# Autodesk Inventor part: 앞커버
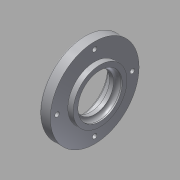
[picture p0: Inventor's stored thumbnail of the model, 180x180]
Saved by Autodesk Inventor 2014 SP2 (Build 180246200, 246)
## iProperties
Created: 2015-09
Part Number: 앞커버
Material: 알루미늄 6061
Document SubType Name: Modeling
Designer: mduedu
Density: 2.71 g/cm^3
Mass: 58.9874 g
Surface Area: 98.7754 cm^2
Volume: 21.7666 cm^3
Appearance: 알루미늄 - 평지
Author: mduedu
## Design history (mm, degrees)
sketch "스케치1"
  geometry: L1 (-8, 67)-(-12, 67); L2 (-12, 67)-(-12, 80); L3 (-12, 80)-(-20, 80); L4 (-20, 80)-(-20, 70.5); L5 (-23, 70.5)-(-23, 61); L6 (-23, 61)-(-8, 61); L7 (-8, 61)-(-8, 67); L8 (-79.5, 39.5)-(-79.5, 54.5) reference; L9 (48.5, 54.5)-(48.5, 39.5) reference; L10 (-79.5, 47)-(48.5, 47); L11 (-20, 70.5)-(-23, 70.5); 3 further points
  constraints: 18 end point, 6 parallel, 4 midpoint, 1 horizontal, 1 perpendicular, 1 vertical alignment
  dimensions: "d0" = 15 distance between parallel lines of L7 L5; "d2" = 28 diameter of L6 L10; "d3" = 40 diameter of L1 L10; "d5" = 4 distance of L1.start L1.end; "d6" = 66 diameter of L3 L10; "d7" = 8 distance of L2.end L3.end; "d8" = 47 diameter of L4.end L10
revolve "회전1" sketch "스케치1" stored, may be unused: angle "d4" = 90 deg
sketch "스케치2"
  geometry: C1 r 33 at (0, 0) reference; 2 further points
  constraints: 1 coincident
hole "구멍1" sketch "스케치2" at (0, 0) diameter "d11" = 33; stored, may be unused: countersink angle "d15" = 90 deg, drill point angle "d17" = 0 deg; dims "d12" = 6, "d13" = 4, "d14" = 2, "d16" = 4
fillet "모깎기1" dims "d18" = 3
fillet "모깎기2" dims "d19" = 1
sketch "스케치3"
  geometry: C1 r 33 at (0, 0) reference; 2 further points
  constraints: 1 coincident
hole "구멍2" sketch "스케치3" at (0, 0) diameter "d20" = 40; stored, may be unused: countersink angle "d24" = 90 deg, drill point angle "d26" = 0 deg; dims "d21" = 6, "d22" = 4, "d23" = 2, "d25" = 8
fillet "모깎기3" dims "d27" = 0.4
chamfer "모따기1" distance "d28" = 1; stored, may be unused: second distance "d29" = 2, angle "d30" = 30 deg
sketch "스케치4" dims "d31" = 56
  geometry: C1 r 33 at (0, 0) reference; 6 further points
  constraints: 2 vertical alignment, 1 coincident, 7 other
  dimensions: "d36" = 360 deg dimension on C1.centre point (0, 28) (derived)
sketch "스케치7"
  geometry: 4 further points
hole "구멍4" sketch "스케치7" at (0, 28), (-28, 0), (28, 0), (0, -28) diameter "d48" = 3.4; stored, may be unused: countersink angle "d52" = 90 deg, drill point angle "d54" = 0 deg; dims "d49" = 6, "d50" = 6.5, "d51" = 3.4, "d53" = 8
node "솔리드1"
node "참조1"
node "참조2"
